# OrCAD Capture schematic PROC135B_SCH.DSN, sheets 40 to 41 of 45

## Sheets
40 40. IO EXPANDER: size C; title: IO EXPANDER AND MCASP1 FET SWITCH AND BUFFER
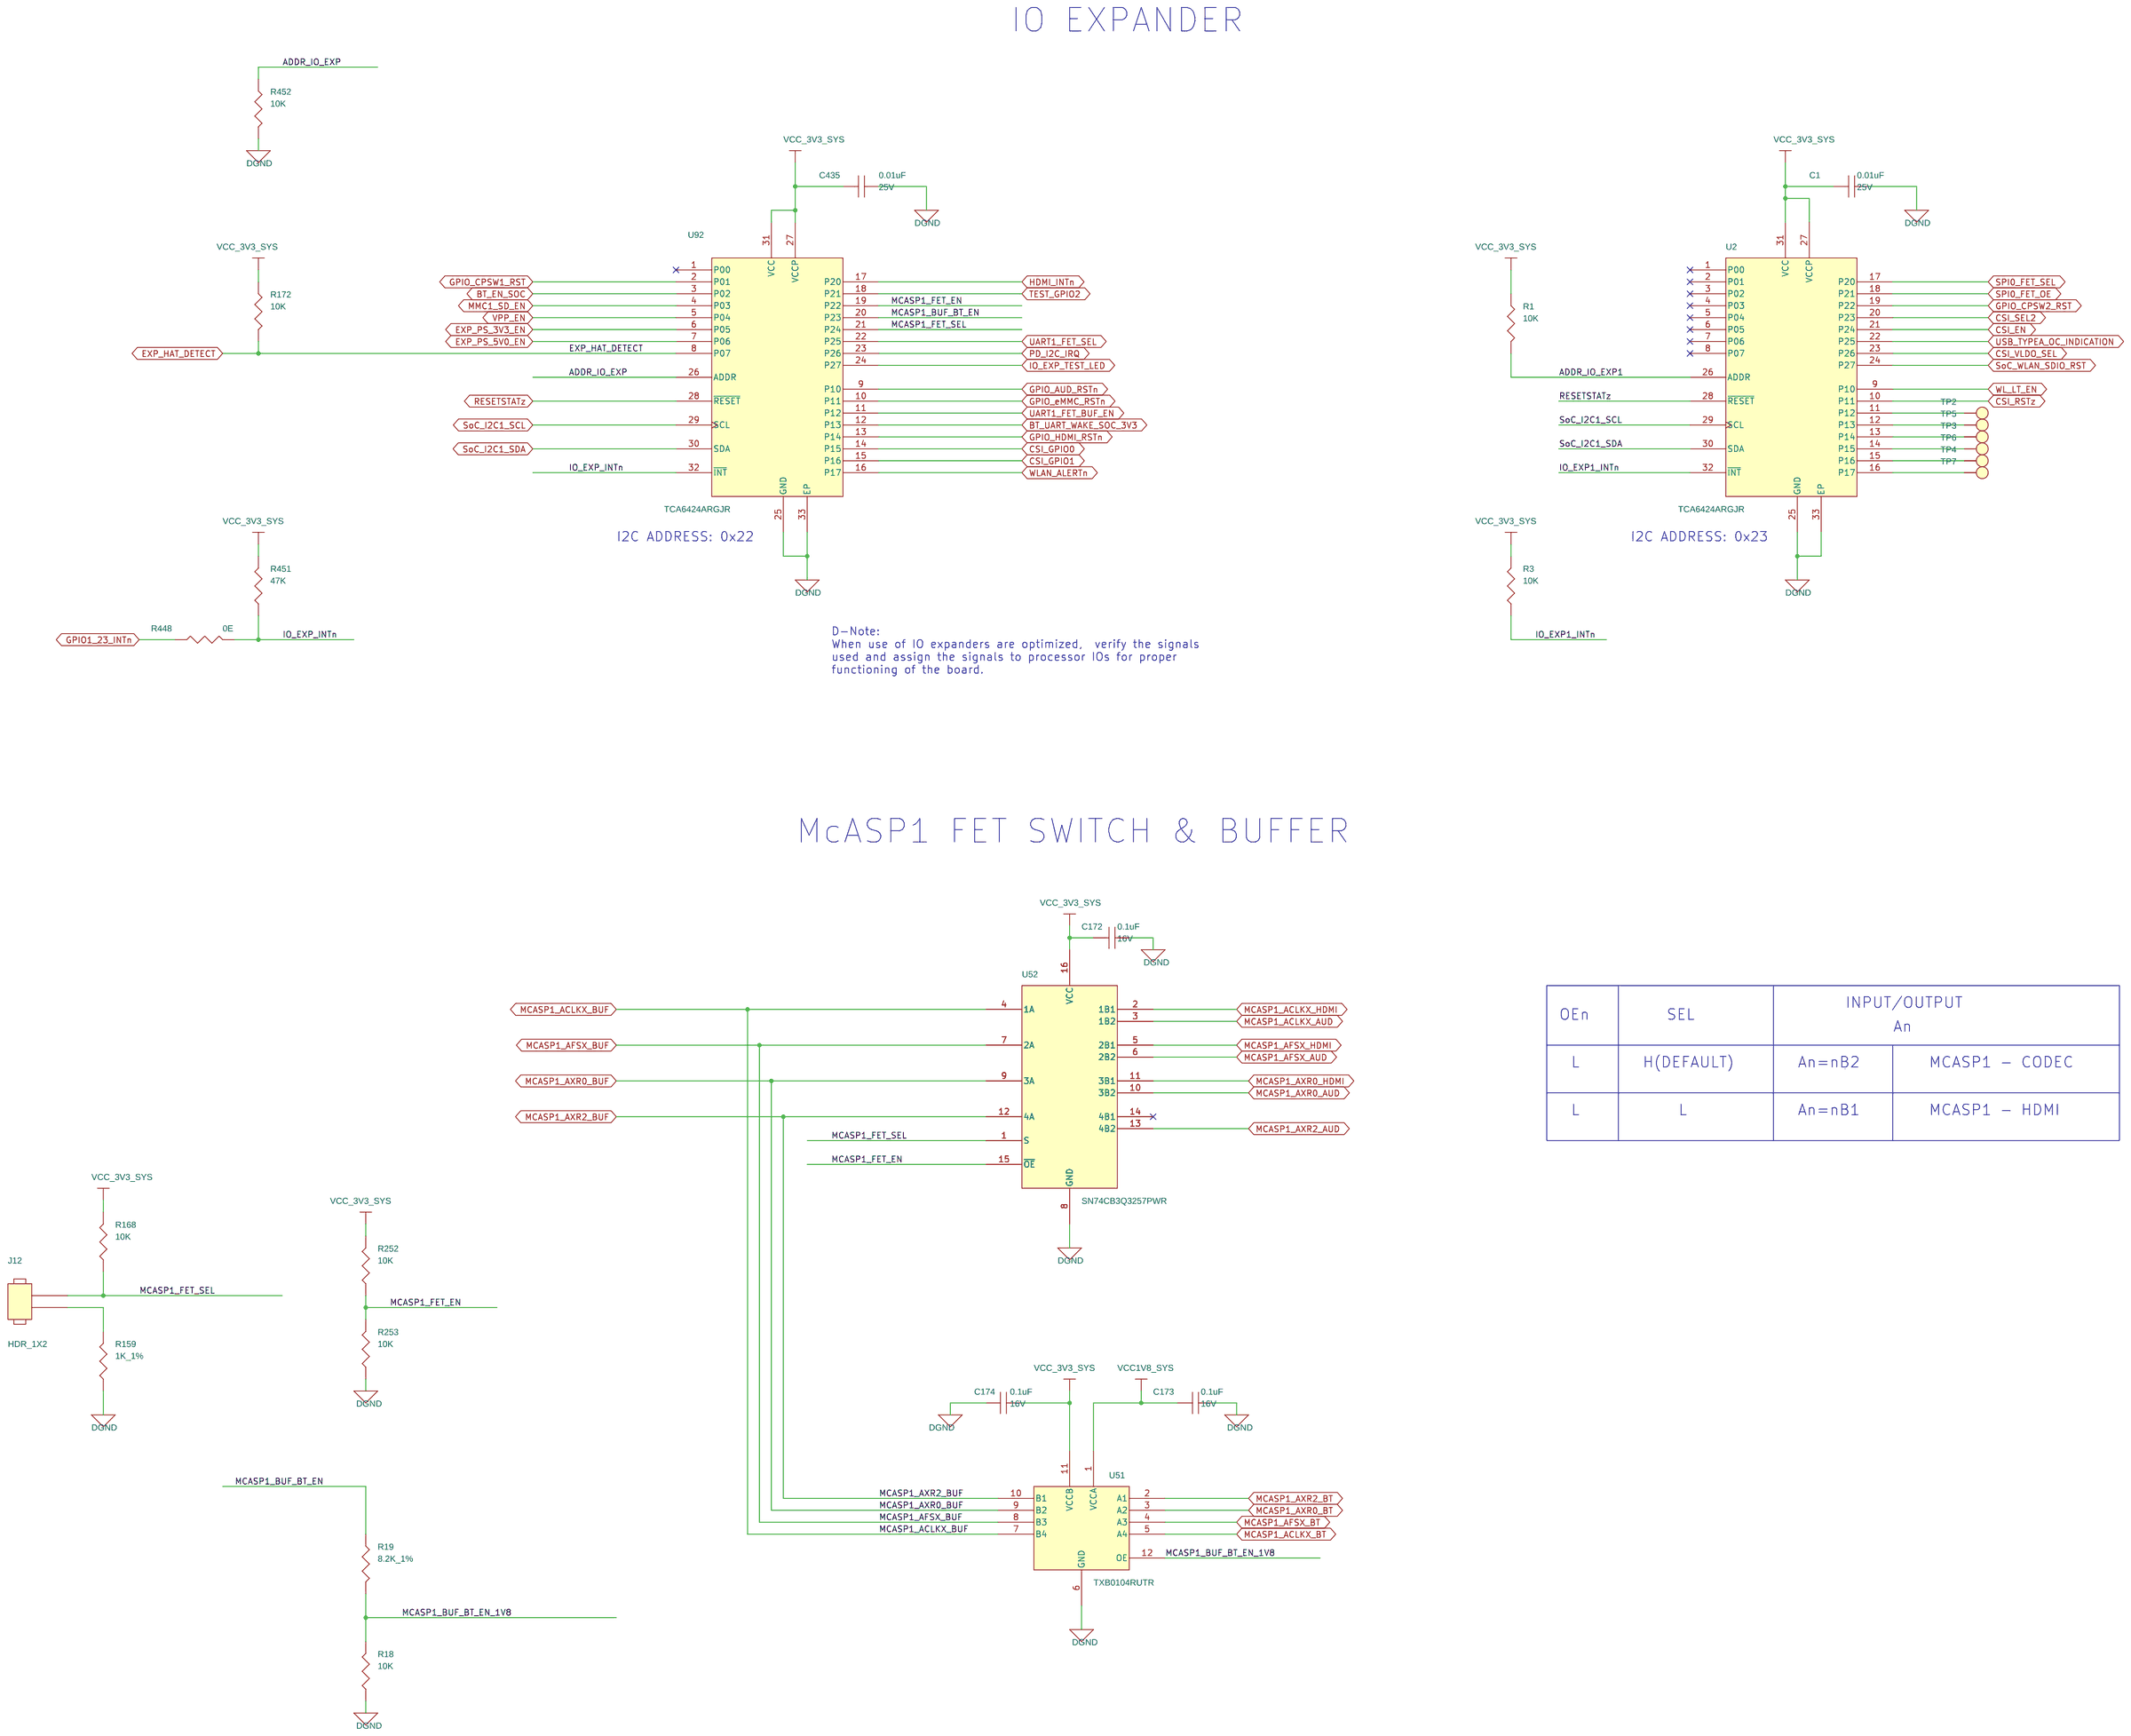
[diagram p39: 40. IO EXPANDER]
41 41. HDMI INTERFACE: size C; title: SOC DPI INTERFACE, DPI TO HDMI TRANSMITTER INTERFACE
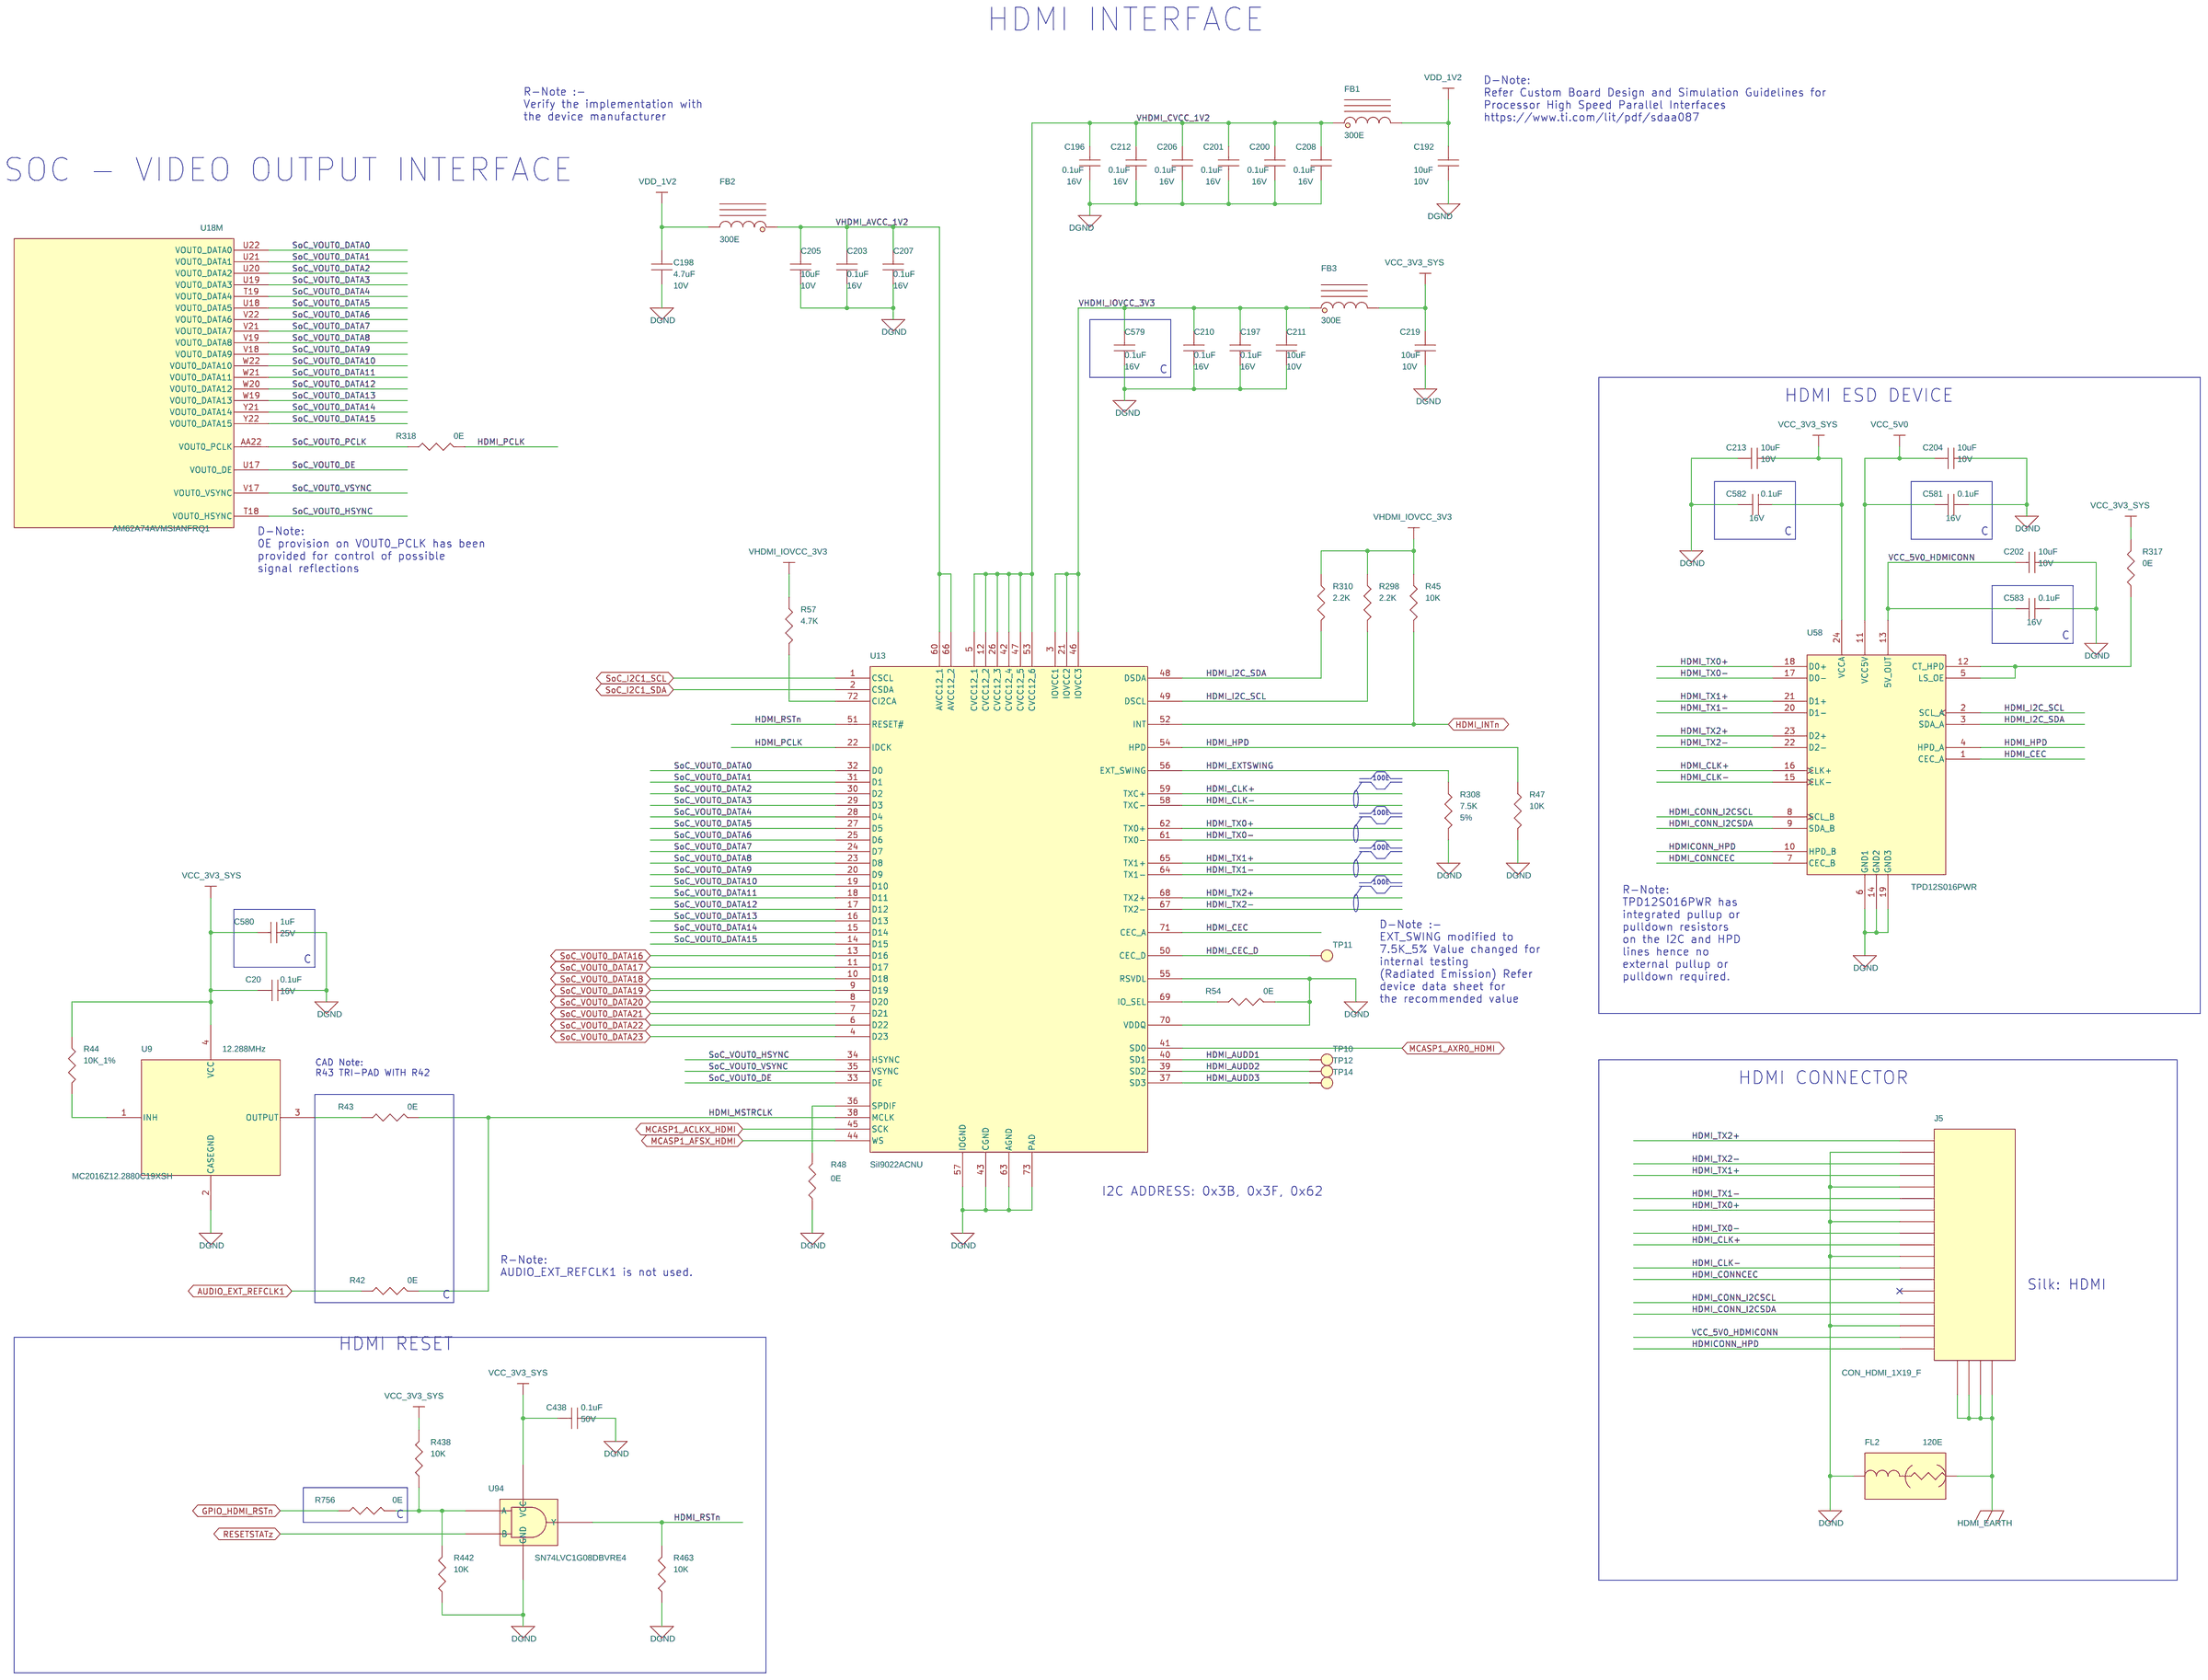
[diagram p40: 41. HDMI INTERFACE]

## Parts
sheet 34. MCU HEADER
U18  AM62A74AVMSIANFRQ1  [FBGA484_31-49_710X710_2-7]  (sections A,B,C,D,E,F,G,H,I,J,K,L,M,N,O,P,Q)
sheet 40. IO EXPANDER
C1  0.01uF  [CAP0201_0-5]
C172  0.1uF  [CAP0201_0-5]
C173  0.1uF  [CAP0201_0-5]
C174  0.1uF  [CAP0201_0-5]
C435  0.01uF  [CAP0201_0-5]
J12  HDR_1X2  [HDR_1X2_90120-0122_S_T_5-6]
R1  10K  [RES0201_0-5]
R3  10K  [RES0201_0-5]
R18  10K  [RES0201_0-5]
R19  8.2K_1%  [RES0201_0-5]
R159  1K_1%  [RES0402_0-5]
R168  10K  [RES0201_0-5]
R172  10K  [RES0201_0-5]
R252  10K  [RES0201_0-5]
R253  10K  [RES0201_0-5]
R448  0E  [RES0201_0-5]
R451  47K  [RES0201_0-5]
R452  10K  [RES0201_0-5]
TP2  TP20_SMD  [TP20_SMD]
TP3  TP20_SMD  [TP20_SMD]
TP4  TP20_SMD  [TP20_SMD]
TP5  TP20_SMD  [TP20_SMD]
TP6  TP20_SMD  [TP20_SMD]
TP7  TP20_SMD  [TP20_SMD]
U2  TCA6424ARGJR  [QFN32_19-68_200X200]
U51  TXB0104RUTR  [UQFN12_TXB0104RUT_70X80_0-6]
U52  SN74CB3Q3257PWR  [TSSOP16_25-59_205X180]
U92  TCA6424ARGJR  [QFN32_19-68_200X200]
sheet 41. HDMI INTERFACE
C20  0.1uF  [CAP0201_0-5]
C192  10uF  [CAP0402_0-75]
C196  0.1uF  [CAP0201_0-5]
C197  0.1uF  [CAP0201_0-5]
C198  4.7uF  [CAP0402_0-75]
C200  0.1uF  [CAP0201_0-5]
C201  0.1uF  [CAP0201_0-5]
C202  10uF  [CAP0402_0-75]
C203  0.1uF  [CAP0201_0-5]
C204  10uF  [CAP0402_0-75]
C205  10uF  [CAP0402_0-75]
C206  0.1uF  [CAP0201_0-5]
C207  0.1uF  [CAP0201_0-5]
C208  0.1uF  [CAP0201_0-5]
C210  0.1uF  [CAP0201_0-5]
C211  10uF  [CAP0402_0-75]
C212  0.1uF  [CAP0201_0-5]
C213  10uF  [CAP0402_0-75]
C219  10uF  [CAP0402_0-75]
C438  0.1uF  [CAP0402_0-75]
C579  0.1uF  [CAP0201_0-5]
C580  1uF  [CAP0402_0-75]
C581  0.1uF  [CAP0201_0-5]
C582  0.1uF  [CAP0201_0-5]
C583  0.1uF  [CAP0201_0-5]
FB1  300E  [IND0603]
FB2  300E  [IND0603]
FB3  300E  [IND0603]
FL2  120E  [EMIFIL_BLM15A_0402_0-6]
J5  CON_HDMI_1X19_F  [CON_19X1_10029449-001RLF_S_R_S_6-3]
R42  0E  [RES0201_0-5]
R43  0E  [RES0201_0-5]
R44  10K_1%  [RES0201_0-5]
R45  10K  [RES0201_0-5]
R47  10K  [RES0201_0-5]
R48  0E  [RES0201_0-5]
R54  0E  [RES0201_0-5]
R57  4.7K  [RES0201_0-5]
R298  2.2K  [RES0402_0-5]
R308  7.5K  [RES0402_0-5]
R310  2.2K  [RES0402_0-5]
R317  0E  [RES0201_0-5]
R318  0E  [RES0201_0-5]
R438  10K  [RES0201_0-5]
R442  10K  [RES0201_0-5]
R463  10K  [RES0201_0-5]
R756  0E  [RES0201_0-5]
TP10  TP20_SMD  [TP20_SMD]
TP11  TP20_SMD  [TP20_SMD]
TP12  TP20_SMD  [TP20_SMD]
TP14  TP20_SMD  [TP20_SMD]
U9  12.288MHz  [OSC4_KC2016K_80X60_SMD_0-8]
U13  SiI9022ACNU  [QFN72_19-68_390X390_0-9]
U58  TPD12S016PWR  [TSSOP24_25-59_315X180_1-2]
U94  SN74LVC1G08DBVRE4  [SOT23-5]

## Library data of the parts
U18 = AM62A-EVM_SOC_FCBGA484: IC AM62A SK EVM SoC MICROPROCESSOR FCBGA484; Chkd/date: PRADEEP/120225; Crtd /date: SHANKARI/120225; Custom_Duty: 15%; Customs_HS_Code: 85369090; Distributor_name: NA; Distributor_part_number: NA; Footprint Path: Y:\MIS_DATABASE\Library\ALTIUM_TOOL\PCB_FOOTPRINTS\Altium_Footprint_Lib.PcbLib; Height: 2.65MM; Library Path: Y:\MIS_DATABASE\Library\ALTIUM_TOOL\SCHEMATICS_PARTS\MS_MICROPROCESSOR_Library.schlib; Library Ref: AM62A-EVM_SoC_FCBGA484; Mfr_name: TEXAS INSTRUMENTS; Mistral Part No: 141225020003-R; Package: FCBGA484; Part_type: ICS\DIGITAL\MICROPROCESSOR; Project: AM62A_SK_EVM; RoHS: NA; Temperature: NA; Tolerance: NA; Voltage: NA; Wattage: NA; Weight: NA; Datasheet: Y:\MIS_DATABASE\DATASHEETS\ICS\DIGITAL\MICROCONTROLLER\AM62A_SK_EVM.PDF
C1 C435 = CAP: CAP CERAMIC 0.01uF 25V 10% X5R AUTO 0201; Chkd/date: MANIRAJA/311221; Crtd /date: ALVY/301221; Custom_Duty: 15%; Customs_HS_Code: 85322990; Distributor_name: MOUSER; Distributor_part_number: 81-GRT033R61E103KE1D; Footprint Path: Y:\MIS_DATABASE\Library\ALTIUM_TOOL\PCB_FOOTPRINTS\Altium_Footprint_Lib.PcbLib; Height: 0.33MM; Library Path: Y:\MIS_DATABASE\Library\ALTIUM_TOOL\SCHEMATICS_PARTS\MS_DISCRETE_Library.schlib; Mfr_name: MURATA; Mfr_part_number: GRT033R61E103KE01D; Mistral Part No: 120021120019-R; Package: 0201; Part_type: CAPACITORS\CERAMIC; Project: AM62Q_SKEVM_BRD; RoHS: RoHS; Temperature: -55°C+85°C; Tolerance: 10%; Voltage: 25V; Wattage: NA; Weight: 0.33mg; Datasheet: Y:\MIS_DATABASE\DATASHEETS\CAPACITORS\GRT033R61E103KE01.PDF
C20 C172-C174 = CAP: CAP CERAMIC 0.1uF 16V 10% X5R 0201; Alt_Mfr_name: YAGEO AMERICA; Alt_Mfr_part_number: CC0402KRX5R8BB104; Chkd/date: PRADEEP/130623; Crtd /date: PRADEEP/130623; Custom_Duty: 15%; Customs_HS_Code: 85322990; Distributor_name: NA; Distributor_part_number: NA; Footprint Path: Y:\MIS_DATABASE\Library\ALTIUM_TOOL\PCB_FOOTPRINTS\Altium_Footprint_Lib.PcbLib; Height: 0.33MM; Library Path: Y:\MIS_DATABASE\Library\ALTIUM_TOOL\SCHEMATICS_PARTS\MS_DISCRETE_Library.schlib; Mfr_name: MURATA; Mfr_part_number: GRT033R61C104KE01; Mistral Part No: 120022060019-R; Package: 0201; Part_type: CAPACITORS\CERAMIC; Project: AM62P_SK; RoHS: RoHS; Temperature: -55°C+85°C; Tolerance: 10%; Voltage: 16V; Wattage: NA; Weight: 0.33mg; Datasheet: Y:\MIS_DATABASE\DATASHEETS\CAPACITORS\GRT033R61C104KE01XX.PDF
J12 = HEADER_2X1: CON HDR 1X2 2.54MM PITCH ST TH; Chkd/date: NAVEED/210714; Crtd /date: USMAN/031012; Custom_Duty: 24%; Customs_HS_Code: 85369090; Distributor_name: DIGIKEY; Distributor_part_number: WM8072-ND; Footprint Path: Y:\MIS_DATABASE\Library\ALTIUM_TOOL\PCB_FOOTPRINTS\Altium_Footprint_Lib.PcbLib; Height: 5.60MM; Library Path: Y:\MIS_DATABASE\Library\ALTIUM_TOOL\SCHEMATICS_PARTS\MS_CONNECTOR_Library.schlib; Mfr_name: MOLEX; Mfr_part_number: 90120-0122; Mistral Part No: 150012100005-R; Package: THRU-HOLE; Part_type: CONNECTOR\HEADERS; Project: NPOL_FEP; RoHS: RoHS; Temperature: -55°C+125°C; Tolerance: NA; Voltage: NA; Wattage: NA; Weight: 122mg; Datasheet: Y:\MIS_DATABASE\DATASHEETS\CONNECTORS\90120-XX.PDF
R1 R3 R18 R45 R47 R168 R172 R252 R253 R438 R442 R452 R463 = RESISTOR: RES 10K 1/20W 5% 0201; Chkd/date: MANIRAJA/050517; Crtd /date: MANIRAJA/050517; Custom_Duty: 15%; Customs_HS_Code: 85332119; Distributor_name: DIGIKEY; Distributor_part_number: 311-10KNCT-ND; Footprint Path: Y:\MIS_DATABASE\Library\ALTIUM_TOOL\PCB_FOOTPRINTS\Altium_Footprint_Lib.PcbLib; Height: 0.26MM; Library Path: Y:\MIS_DATABASE\Library\ALTIUM_TOOL\SCHEMATICS_PARTS\MS_DISCRETE_Library.schlib; Mfr_name: YAGEO AMERICA; Mfr_part_number: RC0201JR-0710KL; Mistral Part No: 110010070051-R; Package: 0201; Part_type: RESISTORS\FIXED; Project: GOLDEN-I LITE; RoHS: RoHS; Temperature: -55°C+125°C; Tolerance: 5%; Voltage: NA; Wattage: 1/20W; Weight: 0.17mg; Datasheet: Y:\MIS_DATABASE\DATASHEETS\RESISTORS\RCXXXXL-SER_MAR18.PDF
R19 = RESISTOR: RES 8.2K 1/20W 1% 0201; Chkd/date: SUHAS/230910; Crtd /date: MUDDU/060710; Custom_Duty: 15%; Customs_HS_Code: 85332119; Distributor_name: DIGIKEY; Distributor_part_number: 541-8.20KAABCT-ND; Footprint Path: Y:\MIS_DATABASE\Library\ALTIUM_TOOL\PCB_FOOTPRINTS\Altium_Footprint_Lib.PcbLib; Height: 0.28MM; Library Path: Y:\MIS_DATABASE\Library\ALTIUM_TOOL\SCHEMATICS_PARTS\MS_DISCRETE_Library.schlib; Mfr_name: VISHAY; Mfr_part_number: CRCW02018K20FKED; Mistral Part No: 110010070001-R; Package: 0201; Part_type: RESISTORS\FIXED; Project: PB_BUGBASE; RoHS: RoHS; Temperature: -55°C+155°C; Tolerance: 1%; Voltage: NA; Wattage: 1/20W; Weight: 0.17mg; Datasheet: Y:\MIS_DATABASE\DATASHEETS\RESISTORS\CRCW0201.PDF
R159 = RESISTOR: RES 1K 1/10W 1% 0402; Chkd/date: VASANTHA/281216; Crtd /date: MAZHAR/150506; Custom_Duty: 15%; Customs_HS_Code: 85332119; Distributor_name: DIGIKEY; Distributor_part_number: P1.00KLCT-ND; Footprint Path: Y:\MIS_DATABASE\Library\ALTIUM_TOOL\PCB_FOOTPRINTS\Altium_Footprint_Lib.PcbLib; Height: 0.40MM; Library Path: Y:\MIS_DATABASE\Library\ALTIUM_TOOL\SCHEMATICS_PARTS\MS_DISCRETE_Library.schlib; Mfr_name: PANASONIC-ECG; Mfr_part_number: ERJ-2RKF1001X; Mistral Part No: 110009030411-R; Package: 0402; Part_type: RESISTORS\FIXED; Project: VOCERA; RoHS: RoHS; Temperature: -55°C+155°C; Tolerance: 1%; Voltage: NA; Wattage: 1/10W; Weight: 0.8mg; Datasheet: Y:\MIS_DATABASE\DATASHEETS\RESISTORS\PAN-ERJSER_NOV17.PDF
R42 R43 R48 R54 R317 R448 R756 = RESISTOR: RES 0E 1/20W 5% 0201; Chkd/date: NAVEED/301214; Crtd /date: MUDDU/120710; Custom_Duty: 15%; Customs_HS_Code: 85332119; Distributor_name: DIGIKEY; Distributor_part_number: 311-0.0NCT-ND; Footprint Path: Y:\MIS_DATABASE\Library\ALTIUM_TOOL\PCB_FOOTPRINTS\Altium_Footprint_Lib.PcbLib; Height: 0.26MM; Library Path: Y:\MIS_DATABASE\Library\ALTIUM_TOOL\SCHEMATICS_PARTS\MS_DISCRETE_Library.schlib; Mfr_name: YAGEO AMERICA; Mfr_part_number: RC0201JR-070RL; Mistral Part No: 110010070067-R; Package: 0201; Part_type: RESISTORS\FIXED; Project: PB_BUGBASE; RoHS: RoHS; Temperature: -55°C+125°C; Tolerance: 5%; Voltage: NA; Wattage: 1/20W; Weight: 0.17mg; Datasheet: Y:\MIS_DATABASE\DATASHEETS\RESISTORS\RCXXXXL-SER_MAR18.PDF
R451 = RESISTOR: RES 47K 1/20W 5% 0201; Chkd/date: MAZHAR/121207; Crtd /date: USMAN/121207; Custom_Duty: 15%; Customs_HS_Code: 85332119; Distributor_name: DIGIKEY; Distributor_part_number: P47KAGCT-ND; Footprint Path: Y:\MIS_DATABASE\Library\ALTIUM_TOOL\PCB_FOOTPRINTS\Altium_Footprint_Lib.PcbLib; Height: 0.26MM; Library Path: Y:\MIS_DATABASE\Library\ALTIUM_TOOL\SCHEMATICS_PARTS\MS_DISCRETE_Library.schlib; Mfr_name: PANASONIC-ECG; Mfr_part_number: ERJ-1GEJ473C; Mistral Part No: 110009030881-R; Package: 0201; Part_type: RESISTORS\FIXED; Project: SD_WATERLOO; RoHS: RoHS; Temperature: -55°C+125°C; Tolerance: 5%; Voltage: NA; Wattage: 1/20W; Weight: 0.15mg; Datasheet: Y:\MIS_DATABASE\DATASHEETS\RESISTORS\PAN-ERJXGE-FEB06.PDF
TP2-TP7 = TESTPOINT: TESTPOINT CIR 20 SMD; Chkd/date: SHREESHAIL/171006; Crtd /date: MAZHAR/171006; Custom_Duty: NA; Customs_HS_Code: NA; Distributor_name: NA; Distributor_part_number: NA; Footprint Path: Y:\MIS_DATABASE\Library\ALTIUM_TOOL\PCB_FOOTPRINTS\Altium_Footprint_Lib.PcbLib; Height: NA; Library Path: Y:\MIS_DATABASE\Library\ALTIUM_TOOL\SCHEMATICS_PARTS\MS_DISCRETE_Library.schlib; MECHANICAL 3D STEP FILE: NA; Manufacturer: LOCAL; Mfr_name: LOCAL; Mistral Part No: NA; Package: SMD; Project: BT MODULE_CSRBC04; RoHS: NA; Temperature: NA; Tolerance: NA; Voltage: NA; Wattage: NA; Weight: NA; Datasheet: NA
U2 U92 = TCA6424ARGJR_QFN32: IC I2C I/O EXPANDER 24B UQFN32; Chkd/date: NAVEED/100715; Crtd /date: NAVEED/100914; Custom_Duty: 15%; Customs_HS_Code: 85423100; Distributor_name: DIGIKEY; Distributor_part_number: 296-27844-1-ND; Height: 0.60MM; Mfr_name: TEXAS INSTRUMENTS; Mistral Part No: 141014090009-R; Package: UQFN32; Part_type: ICS\DIGITAL\BUSTRANSCEIVER; Project: ZK_BIOMETRIC; RoHS: RoHS; Temperature: -40°C+85°C; Weight: NA; Datasheet: Y:\MIS_DATABASE\DATASHEETS\ICS\DIGITAL\BUSTRANSCEIVER\TCA6424AR.PDF
U51 = TXB0104RUTR_UQFN12: IC 4-BIT BIDIRECTIONAL VOLTAGE-LEVEL TRANSLATOR UQFN12; Chkd/date: MANIRAJA/281117; Crtd /date: ALVY/271117; Custom_Duty: 15%; Customs_HS_Code: 85423100; Distributor_name: DIGIKEY; Distributor_part_number: 296-25888-1-ND; Height: 0.55MM; Manufacturer: TEXAS INSTRUMENTS; Mfr_name: TEXAS INSTRUMENTS; Mistral Part No: 141017110007-R; Package: UQFN12; Part_type: ICS\INTERFACE\LEVEL TRANSLATOR; Project: RSAPR_TYPE-II_3U-SBC; RoHS: RoHS; Temperature: -40°C+85°C; Tolerance: NA; Voltage: NA; Wattage: NA; Weight: 4.70mg; Datasheet: Y:\MIS_DATABASE\DATASHEETS\ICS\INTERFACE\TXB0104.PDF
U52 = SN74CB3Q3257PWR_TSSOP16: IC 4BIT 1-OF-2 FET MULTIPLEXER/DEMULTIPLEXER TSSOP16; Chkd/date: SUHAS/251010; Crtd /date: USMAN/060109; Custom_Duty: 15%; Customs_HS_Code: 85423100; Distributor_name: DIGIKEY; Distributor_part_number: 296-19138-1-ND; Height: 1.20MM; Manufacturer: TEXAS INSTRUMENTS; Mfr_name: TEXAS INSTRUMENTS; Mistral Part No: 141009030117-R; Package: TSSOP16; Part_type: ICS\DIGITAL\COMBINATIONAL; Project: OMAP_EVM; RoHS: Sb/ Br FREE; Temperature: -40°C+85°C; Datasheet: Y:\MIS_DATABASE\DATASHEETS\ICS\DIGITAL\COMBINATIONAL\SN74CB3Q3257.PDF
C192 C202 C204 C205 C211 C213 C219 = CAP: CAP CERAMIC 10uF 10V 20% X5R 0402; Chkd/date: PRADEEP/130623; Crtd /date: PRADEEP/130623; Custom_Duty: 15%; Customs_HS_Code: 85322990; Distributor_name: NA; Distributor_part_number: NA; Footprint Path: Y:\MIS_DATABASE\Library\ALTIUM_TOOL\PCB_FOOTPRINTS\Altium_Footprint_Lib.PcbLib; Height: 0.55MM; Library Path: Y:\MIS_DATABASE\Library\ALTIUM_TOOL\SCHEMATICS_PARTS\MS_DISCRETE_Library.schlib; Mfr_name: MURATA; Mfr_part_number: GRM155R61A106ME18; Mistral Part No: 120022060018-R; Package: 0402; Part_type: CAPACITORS\CERAMIC; Project: AM62P_SK; RoHS: RoHS; Temperature: -55°C+85°C; Tolerance: 20%; Voltage: 10V; Wattage: NA; Weight: 6mg; Datasheet: Y:\MIS_DATABASE\DATASHEETS\CAPACITORS\MURATA-GXX-SER_NOV17.PDF
C196 C197 C200 C201 C203 C206-C208 C210 C212 C579 C581-C583 = CAP: CAP CERAMIC 0.1uF 16V 10% X5R 0201; Chkd/date: PRADEEP/130623; Crtd /date: PRADEEP/130623; Custom_Duty: 15%; Customs_HS_Code: 85322990; Distributor_name: NA; Distributor_part_number: NA; Footprint Path: Y:\MIS_DATABASE\Library\ALTIUM_TOOL\PCB_FOOTPRINTS\Altium_Footprint_Lib.PcbLib; Height: 0.33MM; Library Path: Y:\MIS_DATABASE\Library\ALTIUM_TOOL\SCHEMATICS_PARTS\MS_DISCRETE_Library.schlib; Mfr_name: MURATA; Mfr_part_number: GRT033R61C104KE01; Mistral Part No: 120022060019-R; Package: 0201; Part_type: CAPACITORS\CERAMIC; Project: AM62P_SK; RoHS: RoHS; Temperature: -55°C+85°C; Tolerance: 10%; Voltage: 16V; Wattage: NA; Weight: 0.33mg; Datasheet: Y:\MIS_DATABASE\DATASHEETS\CAPACITORS\GRT033R61C104KE01XX.PDF
C198 = CAP: CAP CERAMIC 4.7uF 10V 20% X5R AUTO 0402; Chkd/date: MANIRAJA/250221; Crtd /date: ALVY/240221; Custom_Duty: 15%; Customs_HS_Code: 85322990; Distributor_name: MOUSER; Distributor_part_number: 81-GRT155R61A475ME13; Footprint Path: Y:\MIS_DATABASE\Library\ALTIUM_TOOL\PCB_FOOTPRINTS\Altium_Footprint_Lib.PcbLib; Height: 0.65MM; Library Path: Y:\MIS_DATABASE\Library\ALTIUM_TOOL\SCHEMATICS_PARTS\MS_DISCRETE_Library.schlib; Mfr_name: MURATA; Mfr_part_number: GRT155R61A475ME13D; Mistral Part No: 120021020032-R; Package: 0402; Part_type: CAPACITORS\CERAMIC; Project: TI_DRA821 SK EVM BRD; RoHS: RoHS; Temperature: -55°C+85°C; Tolerance: 20%; Voltage: 10V; Wattage: NA; Weight: 1.5mg; Datasheet: Y:\MIS_DATABASE\DATASHEETS\CAPACITORS\GRT155R61A475ME13.PDF
C438 = CAP: CAP CERAMIC 0.1uF 50V 10% X7R AUTO 0402; Alt_Mfr_name: YAGEO AMERICA; Alt_Mfr_part_number: CC0402KRX5R8BB104; Chkd/date: MANIRAJA/250221; Crtd /date: ALVY/240221; Custom_Duty: 15%; Customs_HS_Code: 85322990; Distributor_name: MOUSER; Distributor_part_number: 81-GRT155R71H104KE1D; Footprint Path: Y:\MIS_DATABASE\Library\ALTIUM_TOOL\PCB_FOOTPRINTS\Altium_Footprint_Lib.PcbLib; Height: 0.55MM; Library Path: Y:\MIS_DATABASE\Library\ALTIUM_TOOL\SCHEMATICS_PARTS\MS_DISCRETE_Library.schlib; Mfr_name: MURATA; Mfr_part_number: GRT155R71H104KE01D; Mistral Part No: 120019030005-R; Package: 0402; Part_type: CAPACITORS\CERAMIC; Project: TI_DRA821 SK EVM BRD; RoHS: RoHS; Temperature: -55°C+125°C; Tolerance: 10%; Voltage: 50V; Wattage: NA; Weight: NA; Datasheet: Y:\MIS_DATABASE\DATASHEETS\CAPACITORS\GRT155R71H104KE01.PDF
C580 = CAP: CAP CERAMIC 1uF 25V 10% X5R AUTO 0402; Chkd/date: MANIRAJA/290318; Crtd /date: ALVY/280318; Custom_Duty: 15%; Customs_HS_Code: 85322990; Distributor_name: DIGIKEY; Distributor_part_number: 490-12263-1-ND; Footprint Path: Y:\MIS_DATABASE\Library\ALTIUM_TOOL\PCB_FOOTPRINTS\Altium_Footprint_Lib.PcbLib; Height: 0.55MM; Library Path: Y:\MIS_DATABASE\Library\ALTIUM_TOOL\SCHEMATICS_PARTS\MS_DISCRETE_Library.schlib; Mfr_name: MURATA; Mfr_part_number: GRT155R61E105KE01D; Mistral Part No: 120019040035-R; Package: 0402; Part_type: CAPACITORS\CERAMIC; Project: NPOL_SAR_ADC; RoHS: RoHS; Temperature: -55°C+85°C; Tolerance: 10%; Voltage: 25V; Wattage: NA; Weight: 0.65mg; Datasheet: Y:\MIS_DATABASE\DATASHEETS\CAPACITORS\GRT155R61E105KE01D.PDF
FB1-FB3 = INDUCTOR_FERRITE: IND FERRITE CHIP 300E 500mA 0603; Alternate_mfr_name_A: TDK CORPORATION; Alternate_mfr_part_number_A: MMZ1608R301ATA00; Chkd/date: VASANTHA/190614; Crtd /date: NAVEED/160614; Custom_Duty: 24%; Customs_HS_Code: 85437099; Distributor_name: DIGIKEY; Distributor_name_A: DIGIKEY; Distributor_part_number: 445-2171-1-ND; Distributor_part_number_A: 445-2171-1-ND; Height: 0.75MM; Mfr_name: TDK CORPORATION; Mfr_part_number: MMZ1608R301A; Mistral Part No: 130014060028-R; Package: 0603; Part_type: INDUCTOR; Project: AEGIS_POM; RoHS: RoHS; Temperature: -55°C+125°C; Tolerance: NA; Voltage: NA; Wattage: NA; Weight: NA; Datasheet: Y:\MIS_DATABASE\DATASHEETS\DISCRETES\INDUCTORS\MMZSER.PDF
FL2 = EMIFILTER_IND: IND FERRITE BEAD CHIP 120E 2A 0402; Crtd /date: SHANKARI/100425; Custom_Duty: 24%; Customs_HS_Code: 85369090; Distributor_name: DIGIKEY; Distributor_part_number: 490-16505-1-ND; Footprint Path: Y:\MIS_DATABASE\Library\ALTIUM_TOOL\PCB_FOOTPRINTS\Altium_Footprint_Lib.PcbLib; Height: 0.55MM; Library Path: Y:\MIS_DATABASE\Library\ALTIUM_TOOL\SCHEMATICS_PARTS\MS_FILTER_Library.schlib; Mfr_name: MURATA; Mfr_part_number: BLM15PX121SZ1D; Mistral Part No: 130025040021-R; Package: 0402; Part_type: INDUCTOR; Project: XWRL6844_EVM_PROTO; RoHS: RoHS; Temperature: -55°C+125°C; Tolerance: 25%; Voltage: NA; Wattage: NA; Weight: NA; Datasheet: Y:\MIS_DATABASE\DATASHEETS\DISCRETES\INDUCTORS\BLM15PX121SZ1D.PDF
J5 = CON_HDMI_19X1: CON HDMI-A TYPE 1X19 0.50MM PITCH FEMALE RT SMD; Chkd/date: VASANTHA/060117; Crtd /date: MUDDU/060510; Custom_Duty: 24%; Customs_HS_Code: 85369090; Distributor_name: DIGIKEY; Distributor_part_number: 609-1010-1-ND; Footprint Path: Y:\MIS_DATABASE\Library\ALTIUM_TOOL\PCB_FOOTPRINTS\Altium_Footprint_Lib.PcbLib; Height: 6.30MM; Library Path: Y:\MIS_DATABASE\Library\ALTIUM_TOOL\SCHEMATICS_PARTS\MS_CONNECTOR_Library.schlib; Mfr_name: FCI; Mfr_part_number: 10029449-001RLF; Mistral Part No: 150010050001-R; Package: SMD; Part_type: CONNECTOR\HDMI; Project: SHIVA; RoHS: RoHS; Temperature: -20°C+85°C; Tolerance: NA; Voltage: NA; Wattage: NA; Weight: 2700mg; Datasheet: Y:\MIS_DATABASE\DATASHEETS\CONNECTORS\10029449-001RLF.PDF
R44 = RESISTOR: RES 10K 1/20W 1% 0201; Chkd/date: VASANTHA/270117; Crtd /date: MANIRAJA/270117; Custom_Duty: 15%; Customs_HS_Code: 85332119; Distributor_name: DIGIKEY; Distributor_part_number: 311-10.0KMCT-ND; Footprint Path: Y:\MIS_DATABASE\Library\ALTIUM_TOOL\PCB_FOOTPRINTS\Altium_Footprint_Lib.PcbLib; Height: 0.26MM; Library Path: Y:\MIS_DATABASE\Library\ALTIUM_TOOL\SCHEMATICS_PARTS\MS_DISCRETE_Library.schlib; Mfr_name: YAGEO AMERICA; Mfr_part_number: RC0201FR-0710KL; Mistral Part No: 110011040018-R; Package: 0201; Part_type: RESISTORS\FIXED; Project: GOLDEN-I LITE; RoHS: RoHS; Temperature: -55°C+125°C; Tolerance: 1%; Voltage: NA; Wattage: 1/20W; Weight: 0.17mg; Datasheet: Y:\MIS_DATABASE\DATASHEETS\RESISTORS\RCXXXXL-SER_MAR18.PDF
R57 = RESISTOR: RES 4.7K 1/20W 5% 0201; Chkd/date: MANIRAJA/200921; Crtd /date: ALVY/200921; Custom_Duty: 15%; Customs_HS_Code: 85332119; Distributor_name: DIGIKEY; Distributor_part_number: 311-4.7KNCT-ND; Footprint Path: Y:\MIS_DATABASE\Library\ALTIUM_TOOL\PCB_FOOTPRINTS\Altium_Footprint_Lib.PcbLib; Height: 0.26MM; Library Path: Y:\MIS_DATABASE\Library\ALTIUM_TOOL\SCHEMATICS_PARTS\MS_DISCRETE_Library.schlib; Mfr_name: YAGEO AMERICA; Mfr_part_number: RC0201JR-074K7L; Mistral Part No: 110021090007-R; Package: 0201; Part_type: RESISTORS\FIXED; Project: TI_AM62x SKEVM_BRD; RoHS: RoHS; Temperature: -55°C+125°C; Tolerance: 5%; Voltage: NA; Wattage: 1/20W; Weight: 0.17mg; Datasheet: Y:\MIS_DATABASE\DATASHEETS\RESISTORS\RCXXXXL-SER_MAR18.PDF
R298 R310 = RESISTOR: RES 2.2K 1/16W 5% 0402; Chkd/date: VASANTHA/061216; Crtd /date: BAVISH/021210; Custom_Duty: 15%; Customs_HS_Code: 85332119; Distributor_name: DIGIKEY; Distributor_part_number: 311-2.2KJRCT-ND; Footprint Path: Y:\MIS_DATABASE\Library\ALTIUM_TOOL\PCB_FOOTPRINTS\Altium_Footprint_Lib.PcbLib; Height: 0.40MM; Library Path: Y:\MIS_DATABASE\Library\ALTIUM_TOOL\SCHEMATICS_PARTS\MS_DISCRETE_Library.schlib; Mfr_name: YAGEO AMERICA; Mfr_part_number: RC0402JR-072K2L; Mistral Part No: 110010120018-R; Package: 0402; Part_type: RESISTORS\FIXED; Project: TE4; RoHS: RoHS; Temperature: -55°C+155°C; Tolerance: 5%; Voltage: NA; Wattage: 1/16W; Weight: 0.65mg; Datasheet: Y:\MIS_DATABASE\DATASHEETS\RESISTORS\RCXXXXL-SER_MAR18.PDF
R308 = RESISTOR: RES 7.5K 1/16W 5% 0402; Chkd/date: MAZHAR/280108; Crtd /date: USMAN/280108; Custom_Duty: 15%; Customs_HS_Code: 85332119; Distributor_name: DIGIKEY; Distributor_part_number: 541-7.5KJCT-ND; Footprint Path: Y:\MIS_DATABASE\Library\ALTIUM_TOOL\PCB_FOOTPRINTS\Altium_Footprint_Lib.PcbLib; Height: 0.40MM; Library Path: Y:\MIS_DATABASE\Library\ALTIUM_TOOL\SCHEMATICS_PARTS\MS_DISCRETE_Library.schlib; Mfr_name: VISHAY; Mfr_part_number: CRCW04027K50JNED; Mistral Part No: 110009031092-R; Package: 0402; Part_type: RESISTORS\FIXED; Project: TELEMETRY ENCODER; RoHS: RoHS; Temperature: -55°C+155°C; Tolerance: 5%; Voltage: NA; Wattage: 1/16W; Weight: 0.65mg; Datasheet: Y:\MIS_DATABASE\DATASHEETS\RESISTORS\CRCW0603.PDF
R318 = RESISTOR: RES 0E 1/20W 5% 0201; Chkd/date: NAVEED/301214; Crtd /date: MUDDU/120710; Custom_Duty: 15%; Customs_HS_Code: 85332119; Distributor_name: DIGIKEY; Distributor_part_number: 311-0.0NCT-ND; Footprint Path: Y:\MIS_DATABASE\Library\ALTIUM_TOOL\PCB_FOOTPRINTS\Altium_Footprint_Lib.PcbLib; Height: 0.26MM; Library Path: Y:\MIS_DATABASE\Library\ALTIUM_TOOL\SCHEMATICS_PARTS\MS_DISCRETE_Library.schlib; Mfr_name: YAGEO AMERICA; Mfr_part_number: RC0201JR-070RL; Mistral Part No: 110010070067-R; Package: 0201; Part_type: RESISTORS\FIXED; Project: PB_BUGBASE; RoHS: RoHS; SIGNAL_MODEL: RESISTOR_RES0201_0-5_0E_0E; Temperature: -55°C+125°C; Tolerance: 5%; Voltage: NA; Wattage: 1/20W; Weight: 0.17mg; Datasheet: Y:\MIS_DATABASE\DATASHEETS\RESISTORS\RCXXXXL-SER_MAR18.PDF
TP10-TP12 TP14 = TESTPOINT: TESTPOINT CIR 20 SMD; Chkd/date: SHREESHAIL/171006; Crtd /date: MAZHAR/171006; Custom_Duty: NA; Customs_HS_Code: NA; Distributor_name: NA; Distributor_part_number: NA; Footprint Path: Y:\MIS_DATABASE\Library\ALTIUM_TOOL\PCB_FOOTPRINTS\Altium_Footprint_Lib.PcbLib; Height: NA; Library Path: Y:\MIS_DATABASE\Library\ALTIUM_TOOL\SCHEMATICS_PARTS\MS_DISCRETE_Library.schlib; MECHANICAL 3D STEP FILE: NA; Mfr_name: LOCAL; Mistral Part No: NA; Package: SMD; Project: BT MODULE_CSRBC04; RoHS: NA; Temperature: NA; Tolerance: NA; Voltage: NA; Wattage: NA; Weight: NA; Datasheet: NA
U9 = OSC4_KC7050K: OSC 12.288MHz CMOS AUTO SMD; Chkd/date: ALVY/310521; Crtd /date: TAMILARASU/310522; Custom_Duty: 24%; Customs_HS_Code: 85437099; Distributor_name: DIGIKEY; Distributor_part_number: 478-MC2016Z12.2880C19XSHCT-ND; Footprint Path: Y:\MIS_DATABASE\Library\ALTIUM_TOOL\PCB_FOOTPRINTS\Altium_Footprint_Lib.PcbLib; Height: 0.80MM; Library Path: Y:\MIS_DATABASE\Library\ALTIUM_TOOL\SCHEMATICS_PARTS\MS_DISCRETE_Library.schlib; Mfr_name: KYOCERA; Mfr_part_number: MC2016Z12.2880C19XSH; Mistral Part No: 130022050049-R; Package: SMD; Part_type: OSCILLATORS; Project: TI_AM62A_SK_EVM; RoHS: RoHS; Temperature: -40°C+125°C; Tolerance: NA; Voltage: NA; Wattage: NA; Weight: NA; Datasheet: Y:\MIS_DATABASE\DATASHEETS\MISC\CRY_OSC\MC-Z-SER.PDF
U13 = SII9022ACNU_QFN72: IC HDMI TRANSMITTER QFN72; Chkd/date: MANIRAJA/270818; Crtd /date: MUDDU/310510; Custom_Duty: 15%; Customs_HS_Code: 85423100; Distributor_name: NA; Distributor_part_number: NA; Footprint Path: Y:\MIS_DATABASE\Library\ALTIUM_TOOL\PCB_FOOTPRINTS\Altium_Footprint_Lib.PcbLib; Height: 0.90MM; Library Path: Y:\MIS_DATABASE\Library\ALTIUM_TOOL\SCHEMATICS_PARTS\MS_COMBINATIONAL_Library.schlib; Library Ref: SiI9022ACNU_QFN72; Mfr_name: SILICON IMAGE; Mistral Part No: 141010060001; Package: QFN72; Part_type: ICS\DIGITAL\PERIPHERAL; Project: CENTAURUS; RoHS: NA; Temperature: -20°C+85°C; Tolerance: NA; Voltage: NA; Wattage: NA; Weight: NA; Datasheet: Y:\MIS_DATABASE\DATASHEETS\ICS\DIGITAL\PERIPHERAL\SiI9022.PDF
U58 = TPD12S016PW_TSSOP24: IC HDMI COMPANION CHIP WITH I2C LEVEL SHIFTING,12-CH ESD TSSOP24; Chkd/date: MANIRAJA/110917; Crtd /date: BAVISH/180811; Custom_Duty: 15%; Customs_HS_Code: 85423100; Distributor_name: DIGIKEY; Distributor_part_number: 296-29690-1-ND; Height: 1.20MM; Mfr_name: TEXAS INSTRUMENTS; Mistral Part No: 141011080021-R; Package: TSSOP24; Part_type: ICS\INTERFACE; Project: DM385EVM_BASE-BOARD; RoHS: RoHS; Temperature: -40°C+85°C; Tolerance: NA; Voltage: NA; Wattage: NA; Weight: 212mg; Datasheet: Y:\MIS_DATABASE\DATASHEETS\ICS\INTERFACE\TPD12S016.PDF
U94 = SN74LVC1G08DBVRE4_SOT23-5: IC SINGLE 2-INPUT POSITIVE AND GATE SOT23-5; Chkd/date: SUHAS/221010; Crtd /date: USMAN/151008; Custom_Duty: 15%; Customs_HS_Code: 85423100; Distributor_name: DIGIKEY; Distributor_part_number: SN74LVC1G08DBVRE4-ND; Height: 1.45MM; Mfr_name: TEXAS INSTRUMENTS; Mistral Part No: 141009060026-R; Part_type: ICS\DIGITAL\GATES; Project: KHAN_MAIN; RoHS: Sb/ Br FREE; Temperature: -40°C+85°C; Datasheet: Y:\MIS_DATABASE\DATASHEETS\ICS\DIGITAL\GATES\SN74LVC1G08.PDF

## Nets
DGND: C1.1 C20.1 C172.1 C173.1 C174.1 C192.2 C196.2 C197.2 C198.2 C200.2 C201.2 C202.2 C203.2 C204.2 C205.2 C206.2 C207.2 C208.2 C210.2 C211.2 C212.2 C213.1 C219.2 C435.1 C438.2 C579.2 C580.2 C581.2 C582.2 C583.2 FL2.1 J5.2 J5.5 J5.8 J5.11 J5.17 R18.1 R47.2 R48.1 R54.2 R159.1 R253.1 R308.2 R442.1 R452.1 R463.1 U2.25(GND) U2.33(EP) U9.2(CASEGND) U13.43(CGND) U13.55(RSVDL) U13.57(IOGND) U13.63(AGND) U13.70(VDDQ) U13.73(PAD) U51.6(GND) U52.8(GND) U58.6(GND1) U58.14(GND2) U58.19(GND3) U92.25(GND) U92.33(EP) U94.3(GND) ; also on sheet 10 11 12 13 14 15 16 17 18 19 20 21 22 23 24 25 26 27 28 29 30 31 32 33 34 35 36 37 38 39 42 43 44
VCC1V8_SYS: C173.2 U51.1(VCCA) ; also on sheet 13 18 19 21 34 37 39 42
VCC_3V3_SYS: C1.2 C20.2 C172.2 C174.2 C213.2 C219.1 C435.2 C438.1 C580.1 C582.1 FB3.2 R1.2 R3.2 R44.2 R168.2 R172.2 R252.2 R317.2 R438.2 R451.2 U2.27(VCCP) U2.31(VCC) U9.4(VCC) U51.11(VCCB) U52.16(VCC) U58.24(VCCA) U92.27(VCCP) U92.31(VCC) U94.5(VCC) ; also on sheet 10 11 13 14 18 19 20 22 23 24 26 27 29 30 31 33 34 35 36 37 38 39 42 43
VCC_5V0: C204.1 C581.1 U58.11(VCC5V) ; also on sheet 10 11 15 33 35 38
VCC_5V0_HDMICONN: C202.1 C583.1 J5.18 U58.13(5V_OUT)
VDD_1V2: C192.1 C198.1 FB1.2 FB2.2 ; also on sheet 11
ADDR_IO_EXP: R452.2 U92.26(ADDR)
ADDR_IO_EXP1: R1.1 U2.26(ADDR)
AUDIO_EXT_REFCLK1: R42.1 ; also on sheet 33
BT_EN_SOC: U92.3(P02) ; also on sheet 18
BT_UART_WAKE_SOC_3V3: U92.12(P13) ; also on sheet 18
CSI_EN: U2.21(P24) ; also on sheet 38
CSI_GPIO0: U92.14(P15) ; also on sheet 37 38
CSI_GPIO1: U92.15(P16) ; also on sheet 37 38
CSI_RSTz: U2.10(P11) ; also on sheet 37
CSI_SEL2: U2.20(P23) ; also on sheet 38
CSI_VLDO_SEL: U2.23(P26) ; also on sheet 38
EXP_HAT_DETECT: R172.1 U92.8(P07) ; also on sheet 33
EXP_PS_3V3_EN: U92.6(P05) ; also on sheet 33
EXP_PS_5V0_EN: U92.7(P06) ; also on sheet 33
GPIO1_23_INTn: R448.1 ; also on sheet 42 43
GPIO_AUD_RSTn: U92.9(P10) ; also on sheet 39
GPIO_CPSW1_RST: U92.2(P01) ; also on sheet 23
GPIO_CPSW2_RST: U2.19(P22) ; also on sheet 24
GPIO_eMMC_RSTn: U92.10(P11) ; also on sheet 19
GPIO_HDMI_RSTn: R756.1 U92.13(P14)
HDMI_AUDD1: TP10.1(TP) U13.40(SD1)
HDMI_AUDD2: TP12.1(TP) U13.39(SD2)
HDMI_AUDD3: TP14.1(TP) U13.37(SD3)
HDMI_CEC: U13.71(CEC_A) U58.1(CEC_A)
HDMI_CEC_D: TP11.1(TP) U13.50(CEC_D)
HDMI_CLK+: J5.10 U13.59(TXC+) U58.16(CLK+)
HDMI_CLK-: J5.12 U13.58(TXC-) U58.15(CLK-)
HDMI_CONN_I2CSCL: J5.15 U58.8(SCL_B)
HDMI_CONN_I2CSDA: J5.16 U58.9(SDA_B)
HDMI_CONNCEC: J5.13 U58.7(CEC_B)
HDMI_EARTH: FL2.2 J5.20 J5.21 J5.22 J5.23
HDMI_EXTSWING: R308.1 U13.56(EXT_SWING)
HDMI_HPD: R47.1 U13.54(HPD) U58.4(HPD_A)
HDMI_I2C_SCL: R298.2 U13.49(DSCL) U58.2(SCL_A)
HDMI_I2C_SDA: R310.2 U13.48(DSDA) U58.3(SDA_A)
HDMI_INTn: R45.2 U13.52(INT) U92.17(P20)
HDMI_MSTRCLK: R42.2 R43.2 U13.38(MCLK)
HDMI_PCLK: R318.2 U13.22(IDCK)
HDMI_RSTn: R463.2 U13.51(RESET#) U94.4(Y)
HDMI_TX0+: J5.7 U13.62(TX0+) U58.18(D0+)
HDMI_TX0-: J5.9 U13.61(TX0-) U58.17(D0-)
HDMI_TX1+: J5.4 U13.65(TX1+) U58.21(D1+)
HDMI_TX1-: J5.6 U13.64(TX1-) U58.20(D1-)
HDMI_TX2+: J5.1 U13.68(TX2+) U58.23(D2+)
HDMI_TX2-: J5.3 U13.67(TX2-) U58.22(D2-)
HDMICONN_HPD: J5.19 U58.10(HPD_B)
IO_EXP1_INTn: R3.1 U2.32(~{INT})
IO_EXP_INTn: R448.2 R451.1 U92.32(~{INT})
IO_EXP_TEST_LED: U92.24(P27) ; also on sheet 36
MCASP1_ACLKX_AUD: U52.3(1B2) ; also on sheet 39
MCASP1_ACLKX_BT: U51.5(A4) ; also on sheet 18
MCASP1_ACLKX_BUF: U51.7(B4) U52.4(1A) ; also on sheet 32
MCASP1_ACLKX_HDMI: U13.45(SCK) U52.2(1B1)
MCASP1_AFSX_AUD: U52.6(2B2) ; also on sheet 39
MCASP1_AFSX_BT: U51.4(A3) ; also on sheet 18
MCASP1_AFSX_BUF: U51.8(B3) U52.7(2A) ; also on sheet 32
MCASP1_AFSX_HDMI: U13.44(WS) U52.5(2B1)
MCASP1_AXR0_AUD: U52.10(3B2) ; also on sheet 39
MCASP1_AXR0_BT: U51.3(A2) ; also on sheet 18
MCASP1_AXR0_BUF: U51.9(B2) U52.9(3A) ; also on sheet 32
MCASP1_AXR0_HDMI: U13.41(SD0) U52.11(3B1)
MCASP1_AXR2_AUD: U52.13(4B2) ; also on sheet 39
MCASP1_AXR2_BT: U51.2(A1) ; also on sheet 18
MCASP1_AXR2_BUF: U51.10(B1) U52.12(4A) ; also on sheet 32
MCASP1_BUF_BT_EN: R19.1 U92.20(P23)
MCASP1_BUF_BT_EN_1V8: R18.2 R19.2 U51.12(OE)
MCASP1_FET_EN: R252.1 R253.2 U52.15(~{OE}) U92.19(P22)
MCASP1_FET_SEL: J12.1 R168.1 U52.1(S) U92.21(P24)
MMC1_SD_EN: U92.4(P03) ; also on sheet 20
PD_I2C_IRQ: U92.23(P26) ; also on sheet 10
RESETSTATz: U2.28(~{RESET}) U92.28(~{RESET}) U94.2(B) ; also on sheet 19 20 21 23 24 27 38 39 42
SOC_I2C1_SCL: U2.29(SCL) U13.1(CSCL) U92.29(SCL) ; also on sheet 14 22 26 39 42
SOC_I2C1_SDA: U2.30(SDA) U13.2(CSDA) U92.30(SDA) ; also on sheet 14 22 26 39 42
SoC_VOUT0_DATA0: U13.32(D0) U18.U22(VOUT0_DATA0)
SoC_VOUT0_DATA1: U13.31(D1) U18.U21(VOUT0_DATA1)
SoC_VOUT0_DATA2: U13.30(D2) U18.U20(VOUT0_DATA2)
SoC_VOUT0_DATA3: U13.29(D3) U18.U19(VOUT0_DATA3)
SoC_VOUT0_DATA4: U13.28(D4) U18.T19(VOUT0_DATA4)
SoC_VOUT0_DATA5: U13.27(D5) U18.U18(VOUT0_DATA5)
SoC_VOUT0_DATA6: U13.25(D6) U18.V22(VOUT0_DATA6)
SoC_VOUT0_DATA7: U13.24(D7) U18.V21(VOUT0_DATA7)
SoC_VOUT0_DATA8: U13.23(D8) U18.V19(VOUT0_DATA8)
SoC_VOUT0_DATA9: U13.20(D9) U18.V18(VOUT0_DATA9)
SoC_VOUT0_DATA10: U13.19(D10) U18.W22(VOUT0_DATA10)
SoC_VOUT0_DATA11: U13.18(D11) U18.W21(VOUT0_DATA11)
SoC_VOUT0_DATA12: U13.17(D12) U18.W20(VOUT0_DATA12)
SoC_VOUT0_DATA13: U13.16(D13) U18.W19(VOUT0_DATA13)
SoC_VOUT0_DATA14: U13.15(D14) U18.Y21(VOUT0_DATA14)
SoC_VOUT0_DATA15: U13.14(D15) U18.Y22(VOUT0_DATA15)
SoC_VOUT0_DATA16: U13.13(D16) ; also on sheet 32
SoC_VOUT0_DATA17: U13.11(D17) ; also on sheet 32
SoC_VOUT0_DATA18: U13.10(D18) ; also on sheet 32
SoC_VOUT0_DATA19: U13.9(D19) ; also on sheet 32
SoC_VOUT0_DATA20: U13.8(D20) ; also on sheet 32
SoC_VOUT0_DATA21: U13.7(D21) ; also on sheet 32
SoC_VOUT0_DATA22: U13.6(D22) ; also on sheet 32
SoC_VOUT0_DATA23: U13.4(D23) ; also on sheet 32
SoC_VOUT0_DE: U13.33(DE) U18.U17(VOUT0_DE)
SoC_VOUT0_HSYNC: U13.34(HSYNC) U18.T18(VOUT0_HSYNC)
SoC_VOUT0_PCLK: R318.1 U18.AA22(VOUT0_PCLK)
SoC_VOUT0_VSYNC: U13.35(VSYNC) U18.V17(VOUT0_VSYNC)
SoC_WLAN_SDIO_RST: U2.24(P27) ; also on sheet 18
SPI0_FET_OE: U2.18(P21) ; also on sheet 42
SPI0_FET_SEL: U2.17(P20) ; also on sheet 42
TEST_GPIO2: U92.18(P21) ; also on sheet 26 28
UART1_FET_BUF_EN: U92.11(P12) ; also on sheet 37
UART1_FET_SEL: U92.22(P25) ; also on sheet 37
USB_TYPEA_OC_INDICATION: U2.22(P25) ; also on sheet 35
VHDMI_AVCC_1V2: C203.1 C205.1 C207.1 FB2.1 U13.60(AVCC12_1) U13.66(AVCC12_2)
VHDMI_CVCC_1V2: C196.1 C200.1 C201.1 C206.1 C208.1 C212.1 FB1.1 U13.5(CVCC12_1) U13.12(CVCC12_2) U13.26(CVCC12_3) U13.42(CVCC12_4) U13.47(CVCC12_5) U13.53(CVCC12_6)
VHDMI_IOVCC_3V3: C197.1 C210.1 C211.1 C579.1 FB3.1 R45.1 R57.1 R298.1 R310.1 U13.3(IOVCC1) U13.21(IOVCC2) U13.46(IOVCC3)
VPP_EN: U92.5(P04) ; also on sheet 13
WL_LT_EN: U2.9(P10) ; also on sheet 18
WLAN_ALERTn: U92.16(P17) ; also on sheet 18
N16927060: R57.2 U13.72(CI2CA)
N16927228: R54.1 U13.69(IO_SEL)
N16927289: R48.2 U13.36(SPDIF)
N16927312: R438.1 R442.2 R756.2 U94.1(A)
N17285208: R317.1 U58.5(LS_OE) U58.12(CT_HPD)
N19082749: R43.1 U9.3(OUTPUT)
N20936712: J12.2 R159.2
N21197992: TP7.1(TP) U2.16(P17)
N21197993: TP4.1(TP) U2.15(P16)
N21197994: TP3.1(TP) U2.13(P14)
N21197995: TP6.1(TP) U2.14(P15)
N21197996: TP5.1(TP) U2.12(P13)
N21198784: TP2.1(TP) U2.11(P12)
N23413104: R44.1 U9.1(INH)

Not connected (* = marked no-connect by the designer): J5 14*; U2 1(P00)* 2(P01)* 3(P02)* 4(P03)* 5(P04)* 6(P05)* 7(P06)* 8(P07)*; U52 14(4B1)*; U92 1(P00)*

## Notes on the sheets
sheet 40
- IO EXPANDER
- I2C ADDRESS: 0x22
- I2C ADDRESS: 0x23
- D-Note:
  When use of IO expanders are optimized,  verify the signals
  used and assign the signals to processor IOs for proper
  functioning of the board.
- McASP1 FET SWITCH & BUFFER
- INPUT/OUTPUT
- OEn
- SEL
- An
- L
- H(DEFAULT)
- An=nB2
- MCASP1 - CODEC
- L
- L
- An=nB1
- MCASP1 - HDMI
sheet 41
- HDMI INTERFACE
- D-Note:
  Refer Custom Board Design and Simulation Guidelines for
  Processor High Speed Parallel Interfaces
  https://www.ti.com/lit/pdf/sdaa087
- R-Note :-
  Verify the implementation with
  the device manufacturer
- SOC - VIDEO OUTPUT INTERFACE
- C
- HDMI ESD DEVICE
- D-Note:
  0E provision on VOUT0_PCLK has been
  provided for control of possible
  signal reflections
- C
- C
- C
- 100E
- 100E
- 100E
- 100E
- R-Note:
  TPD12S016PWR has
  integrated pullup or
  pulldown resistors
  on the I2C and HPD
  lines hence no
  external pullup or
  pulldown required.
- D-Note :-
  EXT_SWING modified to
  7.5K_5% Value changed for
  internal testing
  (Radiated Emission) Refer
  device data sheet for
  the recommended value
- C
- CAD Note:
  R43 TRI-PAD WITH R42
- HDMI CONNECTOR
- I2C ADDRESS: 0x3B, 0x3F, 0x62
- R-Note:
  AUDIO_EXT_REFCLK1 is not used.
- Silk: HDMI
- C
- HDMI RESET
- C
